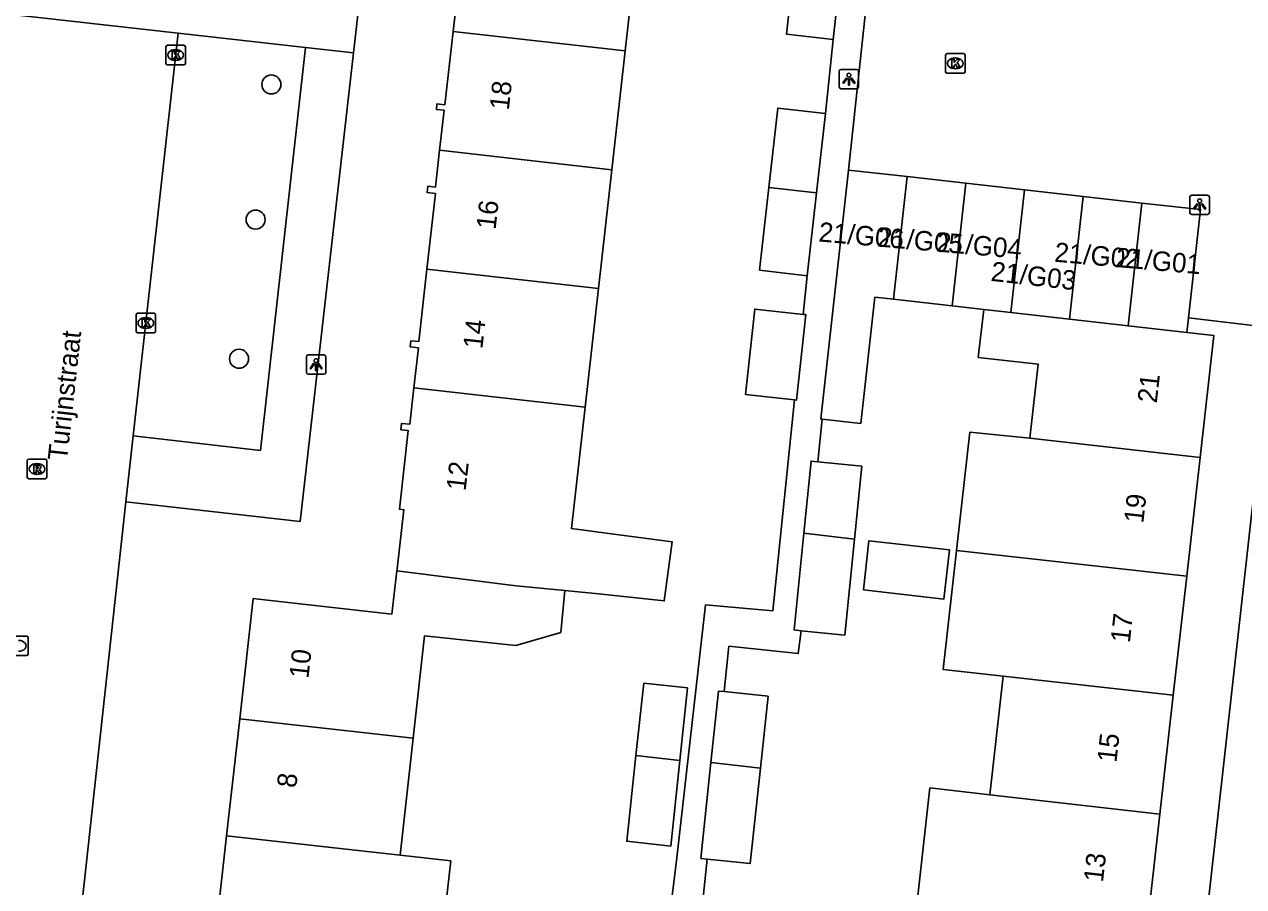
# Model space of a CAD drawing. Extents: x 162082 to 163393, y 388091 to 388632.
# Drawn here: x 162880.7 to 162943.3, y 388368.3 to 388412.6 of the extents above; entities that cross this region are included whole.
import ezdxf

# ---------------------------------------------------------------- set-up
doc = ezdxf.new("R2010")
doc.units = 0
for name, color, linetype in [('IMGEO_Boom', 7, 'Continuous'), ('IMGEO_Kolk', 7, 'Continuous'), ('IMGEO_Lichtpunt', 7, 'Continuous'), ('IMGEO_Openbare_ruimte_label', 7, 'Continuous'), ('IMGEO_Pand', 7, 'Continuous'), ('IMGEO_Pand_nummerreeks', 7, 'Continuous'), ('IMGEO_Rijbaan_lokaal_open', 7, 'Continuous'), ('IMGEO_Rioolput', 7, 'Continuous'), ('IMGEO_Voetpad_open', 7, 'Continuous')]:
    doc.layers.add(name, color=color, linetype=linetype)

msp = doc.modelspace()

# ---------------------------------------------------------------- linework, layer by layer
at = {"layer": 'IMGEO_Boom'}
for centre in [(162893.365, 388409.537), (162892.554, 388402.591), (162891.704, 388395.442)]:
    msp.add_circle(centre, 0.489, dxfattribs=at)
at = {"layer": 'IMGEO_Kolk'}
for p, q in [((162887.945, 388410.622), (162887.945, 388411.474)), ((162888.02, 388411.548), (162888.872, 388411.548)), ((162888.433, 388411.328), (162888.458, 388411.328)), ((162888.946, 388411.474), (162888.946, 388410.622)), ((162888.456, 388410.768), (162888.431, 388410.768)), ((162928.023, 388410.194), (162928.023, 388411.046)), ((162928.098, 388411.12), (162928.95, 388411.12)), ((162928.511, 388410.9), (162928.536, 388410.9)), ((162929.024, 388411.046), (162929.024, 388410.194)), ((162888.872, 388410.548), (162888.02, 388410.548)), ((162928.95, 388410.12), (162928.098, 388410.12)), ((162928.534, 388410.34), (162928.509, 388410.34)), ((162886.41, 388396.852), (162886.41, 388397.704)), ((162886.485, 388397.778), (162887.337, 388397.778)), ((162886.898, 388397.558), (162886.923, 388397.558)), ((162887.411, 388397.704), (162887.411, 388396.852)), ((162886.921, 388396.998), (162886.896, 388396.998)), ((162887.337, 388396.778), (162886.485, 388396.778)), ((162879.932, 388381.188), (162880.784, 388381.188)), ((162880.858, 388381.114), (162880.858, 388380.262)), ((162880.784, 388380.188), (162879.932, 388380.188))]:
    msp.add_line(p, q, dxfattribs=at)
for points in [[(162887.945, 388410.622), (162887.945, 388411.474)], [(162888.02, 388411.548), (162888.872, 388411.548)], [(162888.946, 388411.474), (162888.946, 388410.622)], [(162888.266, 388411.248), (162888.389, 388411.248), (162888.389, 388411.097), (162888.519, 388411.248), (162888.683, 388411.248), (162888.537, 388411.097), (162888.69, 388410.848), (162888.538, 388410.848), (162888.453, 388411.012), (162888.389, 388410.945), (162888.389, 388410.848), (162888.266, 388410.848), (162888.266, 388411.248)], [(162928.023, 388410.194), (162928.023, 388411.046)], [(162928.098, 388411.12), (162928.95, 388411.12)], [(162928.344, 388410.82), (162928.467, 388410.82), (162928.467, 388410.669), (162928.597, 388410.82), (162928.761, 388410.82), (162928.615, 388410.669), (162928.768, 388410.42), (162928.616, 388410.42), (162928.531, 388410.584), (162928.467, 388410.517), (162928.467, 388410.42), (162928.344, 388410.42), (162928.344, 388410.82)], [(162929.024, 388411.046), (162929.024, 388410.194)], [(162888.872, 388410.548), (162888.02, 388410.548)], [(162928.95, 388410.12), (162928.098, 388410.12)], [(162886.41, 388396.852), (162886.41, 388397.704)], [(162886.485, 388397.778), (162887.337, 388397.778)], [(162887.411, 388397.704), (162887.411, 388396.852)], [(162886.731, 388397.478), (162886.854, 388397.478), (162886.854, 388397.327), (162886.984, 388397.478), (162887.148, 388397.478), (162887.002, 388397.327), (162887.155, 388397.078), (162887.003, 388397.078), (162886.918, 388397.242), (162886.854, 388397.175), (162886.854, 388397.078), (162886.731, 388397.078), (162886.731, 388397.478)], [(162887.337, 388396.778), (162886.485, 388396.778)], [(162879.932, 388381.188), (162880.784, 388381.188)], [(162880.858, 388381.114), (162880.858, 388380.262)], [(162880.784, 388380.188), (162879.932, 388380.188)]]:
    msp.add_lwpolyline(points, dxfattribs=at)
for centre, start, end in [((162888.022, 388411.472), 91.55205, 178.44795), ((162888.022, 388411.472), 91.55205, 178.44795), ((162888.87, 388411.472), 1.55205, 88.44795), ((162888.87, 388411.472), 1.55205, 88.44795), ((162928.1, 388411.044), 91.55205, 178.44795), ((162928.1, 388411.044), 91.55205, 178.44795), ((162928.948, 388411.044), 1.55205, 88.44795), ((162928.948, 388411.044), 1.55205, 88.44795), ((162888.022, 388410.624), 181.55205, 268.44795), ((162888.022, 388410.624), 181.55205, 268.44795), ((162888.87, 388410.624), 271.55205, 358.44795), ((162888.87, 388410.624), 271.55205, 358.44795), ((162928.1, 388410.196), 181.55205, 268.44795), ((162928.1, 388410.196), 181.55205, 268.44795), ((162928.948, 388410.196), 271.55205, 358.44795), ((162928.948, 388410.196), 271.55205, 358.44795), ((162886.487, 388397.702), 91.55205, 178.44795), ((162886.487, 388397.702), 91.55205, 178.44795), ((162887.335, 388397.702), 1.55205, 88.44795), ((162887.335, 388397.702), 1.55205, 88.44795), ((162886.487, 388396.854), 181.55205, 268.44795), ((162886.487, 388396.854), 181.55205, 268.44795), ((162887.335, 388396.854), 271.55205, 358.44795), ((162887.335, 388396.854), 271.55205, 358.44795), ((162880.782, 388381.112), 1.55205, 88.44795), ((162880.782, 388381.112), 1.55205, 88.44795), ((162880.782, 388380.264), 271.55205, 358.44795), ((162880.782, 388380.264), 271.55205, 358.44795)]:
    msp.add_arc(centre, 0.0765, start, end, dxfattribs=at)
for centre, major_axis, ratio, start_param, end_param in [((162888.432, 388411.048), (-0.387, 0.002), 0.722429, 4.712389, 7.853982), ((162888.457, 388411.048), (-0.39, 0.002), 0.717154, 1.570796, 4.712389), ((162928.51, 388410.62), (-0.387, 0.002), 0.722429, 4.712389, 7.853982), ((162928.535, 388410.62), (-0.39, 0.002), 0.717154, 1.570796, 4.712389), ((162886.897, 388397.278), (-0.387, 0.002), 0.722429, 4.712389, 7.853982), ((162886.922, 388397.278), (-0.39, 0.002), 0.717154, 1.570796, 4.712389), ((162880.369, 388380.688), (-0.39, 0.002), 0.717154, 1.570796, 4.712389)]:
    msp.add_ellipse(centre, major_axis=major_axis, ratio=ratio, start_param=start_param, end_param=end_param, dxfattribs=at)
at = {"layer": 'IMGEO_Lichtpunt'}
for p, q in [((162922.555, 388410.214), (162922.555, 388409.407)), ((162922.555, 388410.214), (162922.555, 388409.407)), ((162923.457, 388410.309), (162922.649, 388410.309)), ((162923.457, 388410.309), (162922.649, 388410.309)), ((162923.551, 388409.407), (162923.551, 388410.214)), ((162923.551, 388409.407), (162923.551, 388410.214)), ((162922.649, 388409.313), (162923.457, 388409.313)), ((162922.649, 388409.313), (162923.457, 388409.313)), ((162941.486, 388403.849), (162940.678, 388403.849)), ((162941.486, 388403.849), (162940.678, 388403.849)), ((162940.584, 388403.754), (162940.584, 388402.947)), ((162940.584, 388403.754), (162940.584, 388402.947)), ((162941.58, 388402.947), (162941.58, 388403.754)), ((162941.58, 388402.947), (162941.58, 388403.754)), ((162940.678, 388402.853), (162941.486, 388402.853)), ((162940.678, 388402.853), (162941.486, 388402.853)), ((162895.164, 388395.543), (162895.164, 388394.736)), ((162895.164, 388395.543), (162895.164, 388394.736)), ((162896.066, 388395.638), (162895.258, 388395.638)), ((162896.066, 388395.638), (162895.258, 388395.638)), ((162896.16, 388394.736), (162896.16, 388395.543)), ((162896.16, 388394.736), (162896.16, 388395.543)), ((162895.258, 388394.642), (162896.066, 388394.642)), ((162895.258, 388394.642), (162896.066, 388394.642))]:
    msp.add_line(p, q, dxfattribs=at)
for points in [[(162922.929, 388409.878), (162922.968, 388409.85), (162922.78, 388409.588), (162922.742, 388409.615), (162922.929, 388409.878)], [(162923.031, 388409.83), (162923.078, 388409.83), (162923.078, 388409.508), (162923.031, 388409.508), (162923.031, 388409.83)], [(162923.141, 388409.85), (162923.179, 388409.877), (162923.366, 388409.615), (162923.327, 388409.587), (162923.141, 388409.85)], [(162940.958, 388403.418), (162940.997, 388403.39), (162940.809, 388403.128), (162940.771, 388403.155), (162940.958, 388403.418)], [(162941.06, 388403.37), (162941.107, 388403.37), (162941.107, 388403.048), (162941.06, 388403.048), (162941.06, 388403.37)], [(162941.17, 388403.39), (162941.208, 388403.417), (162941.395, 388403.155), (162941.356, 388403.127), (162941.17, 388403.39)], [(162895.538, 388395.207), (162895.577, 388395.179), (162895.389, 388394.917), (162895.351, 388394.944), (162895.538, 388395.207)], [(162895.64, 388395.159), (162895.687, 388395.159), (162895.687, 388394.837), (162895.64, 388394.837), (162895.64, 388395.159)], [(162895.75, 388395.179), (162895.788, 388395.206), (162895.975, 388394.944), (162895.936, 388394.916), (162895.75, 388395.179)]]:
    msp.add_lwpolyline(points, dxfattribs=at)
for centre in [(162923.054, 388410.012), (162941.083, 388403.552), (162895.663, 388395.341)]:
    msp.add_circle(centre, 0.0994, dxfattribs=at)
for centre, start, end in [((162922.649, 388410.214), 90, 180), ((162922.649, 388410.214), 90, 180), ((162923.457, 388410.214), 0, 90), ((162923.457, 388410.214), 0, 90), ((162922.649, 388409.407), 180, 270), ((162922.649, 388409.407), 180, 270), ((162923.457, 388409.407), 270, 0), ((162923.457, 388409.407), 270, 360), ((162940.678, 388403.754), 90, 180), ((162940.678, 388403.754), 90, 180), ((162941.486, 388403.754), 0, 90), ((162941.486, 388403.754), 0, 90), ((162940.678, 388402.947), 180, 270), ((162940.678, 388402.947), 180, 270), ((162941.486, 388402.947), 270, 0), ((162941.486, 388402.947), 270, 360), ((162895.258, 388395.543), 90, 180), ((162895.258, 388395.543), 90, 180), ((162896.066, 388395.543), 0, 90), ((162896.066, 388395.543), 0, 90), ((162895.258, 388394.736), 180, 270), ((162895.258, 388394.736), 180, 270), ((162896.066, 388394.736), 270, 0), ((162896.066, 388394.736), 270, 360)]:
    msp.add_arc(centre, 0.0946, start, end, dxfattribs=at)
at = {"layer": 'IMGEO_Pand'}
for points in [[(162902.702, 388412.256), (162903.148, 388416.214), (162902.781, 388416.255), (162902.811, 388416.521), (162903.195, 388416.477), (162903.406, 388418.355)], [(162912.234, 388417.362), (162911.547, 388411.261)], [(162920.323, 388416.452), (162919.845, 388412.119), (162922.249, 388411.854)], [(162922.726, 388416.182), (162922.249, 388411.854)], [(162902.011, 388406.155), (162902.242, 388408.213), (162901.847, 388408.257), (162901.879, 388408.54), (162902.279, 388408.495), (162902.702, 388412.256)], [(162902.702, 388412.256), (162911.547, 388411.261)], [(162911.547, 388411.261), (162910.861, 388405.158)], [(162918.94, 388404.248), (162919.397, 388408.322), (162921.845, 388408.047)], [(162921.845, 388408.047), (162921.388, 388403.972)], [(162901.361, 388400.05), (162901.798, 388403.932), (162901.367, 388403.98), (162901.404, 388404.306), (162901.798, 388404.262), (162902.011, 388406.155)], [(162910.861, 388405.158), (162902.011, 388406.155)], [(162910.861, 388405.158), (162910.175, 388399.057)], [(162921.673, 388392.337), (162921.601, 388392.345), (162922.33, 388398.836), (162923.038, 388405.139)], [(162923.038, 388405.139), (162926.054, 388404.8)], [(162926.054, 388404.8), (162925.345, 388398.497)], [(162929.069, 388404.461), (162926.054, 388404.8)], [(162929.069, 388404.461), (162928.361, 388398.158)], [(162932.084, 388404.122), (162929.069, 388404.461)], [(162918.94, 388404.248), (162918.461, 388399.985), (162920.909, 388399.71)], [(162921.388, 388403.972), (162918.94, 388404.248)], [(162921.388, 388403.972), (162920.909, 388399.71)], [(162932.084, 388404.122), (162931.376, 388397.819)], [(162935.1, 388403.784), (162932.084, 388404.122)], [(162934.392, 388397.479), (162935.1, 388403.784)], [(162938.116, 388403.445), (162935.1, 388403.784)], [(162937.407, 388397.136), (162938.116, 388403.445)], [(162940.506, 388397.545), (162941.131, 388403.106), (162938.116, 388403.445)], [(162900.69, 388393.946), (162900.921, 388395.998), (162900.502, 388396.045), (162900.538, 388396.369), (162900.942, 388396.323), (162901.361, 388400.05)], [(162901.361, 388400.05), (162910.175, 388399.057)], [(162910.175, 388399.057), (162909.488, 388392.955)], [(162925.345, 388398.497), (162924.387, 388398.605), (162923.658, 388392.114), (162921.673, 388392.337)], [(162928.361, 388398.158), (162925.345, 388398.497)], [(162928.361, 388398.158), (162929.983, 388397.976)], [(162920.255, 388393.333), (162917.737, 388393.606), (162918.213, 388397.992), (162920.705, 388397.722)], [(162920.705, 388397.722), (162920.84, 388397.707), (162920.365, 388393.321), (162920.255, 388393.333)], [(162929.983, 388397.976), (162929.705, 388395.506), (162932.788, 388395.16), (162932.36, 388391.355)], [(162931.376, 388397.819), (162929.983, 388397.976)], [(162931.376, 388397.819), (162934.392, 388397.479)], [(162940.422, 388396.793), (162940.506, 388397.545)], [(162937.407, 388397.136), (162934.392, 388397.479)], [(162940.422, 388396.793), (162937.407, 388397.136)], [(162941.102, 388390.373), (162941.806, 388396.638), (162940.422, 388396.793)], [(162899.813, 388384.536), (162899.826, 388384.65), (162900.177, 388387.679), (162899.946, 388387.705), (162900.401, 388391.746), (162900.022, 388391.789), (162900.059, 388392.122), (162900.479, 388392.074), (162900.69, 388393.946)], [(162909.488, 388392.955), (162900.69, 388393.946)], [(162908.448, 388383.527), (162910.351, 388383.344), (162913.563, 388382.992), (162913.961, 388386.033), (162910.712, 388386.458), (162908.786, 388386.71), (162909.488, 388392.955)], [(162932.36, 388391.355), (162929.274, 388391.674), (162928.59, 388385.584)], [(162932.36, 388391.355), (162941.102, 388390.373)], [(162920.735, 388386.471), (162921.11, 388390.186), (162921.452, 388390.152)], [(162923.337, 388386.178), (162923.714, 388389.924), (162921.452, 388390.152)], [(162940.415, 388384.26), (162941.102, 388390.373)], [(162920.59, 388381.467), (162920.235, 388381.503), (162920.735, 388386.471)], [(162920.735, 388386.471), (162923.337, 388386.178)], [(162920.59, 388381.467), (162922.839, 388381.241), (162923.337, 388386.178)], [(162923.796, 388383.56), (162924.08, 388386.084), (162928.223, 388385.625), (162927.939, 388383.094), (162923.796, 388383.56)], [(162928.59, 388385.584), (162927.904, 388379.474), (162930.986, 388379.128)], [(162940.415, 388384.26), (162931.673, 388385.242), (162928.59, 388385.584)], [(162891.739, 388376.944), (162892.43, 388383.113), (162893.007, 388383.048), (162899.555, 388382.315), (162899.813, 388384.536)], [(162908.448, 388383.527), (162905.942, 388383.767), (162899.813, 388384.536)], [(162939.729, 388378.146), (162940.415, 388384.26)], [(162900.655, 388375.945), (162901.243, 388381.196), (162905.937, 388380.699), (162908.242, 388381.377), (162908.448, 388383.527)], [(162912.105, 388375.059), (162912.503, 388378.769), (162914.762, 388378.527), (162914.362, 388374.794)], [(162930.302, 388373.037), (162930.986, 388379.128)], [(162930.986, 388379.128), (162939.729, 388378.146)], [(162915.963, 388374.684), (162916.354, 388378.366), (162916.638, 388378.336)], [(162918.502, 388374.393), (162918.894, 388378.097), (162916.638, 388378.336)], [(162939.729, 388378.146), (162939.042, 388372.033)], [(162891.065, 388370.923), (162891.739, 388376.944)], [(162891.739, 388376.944), (162900.655, 388375.945)], [(162900.655, 388375.945), (162899.981, 388369.924)], [(162914.362, 388374.794), (162913.892, 388370.4), (162911.632, 388370.642), (162912.105, 388375.059)], [(162912.105, 388375.059), (162914.362, 388374.794)], [(162915.764, 388369.733), (162915.442, 388369.767), (162915.963, 388374.684)], [(162915.764, 388369.733), (162917.982, 388369.497), (162918.502, 388374.393)], [(162915.963, 388374.684), (162918.502, 388374.393)], [(162930.302, 388373.037), (162927.218, 388373.384), (162926.526, 388367.229)], [(162939.042, 388372.033), (162930.302, 388373.037)], [(162938.355, 388365.919), (162939.042, 388372.033)], [(162890.391, 388364.901), (162891.065, 388370.923)], [(162891.065, 388370.923), (162899.981, 388369.924)], [(162899.981, 388369.924), (162902.587, 388369.632), (162901.913, 388363.61)]]:
    msp.add_lwpolyline(points, dxfattribs=at)
at = {"layer": 'IMGEO_Rijbaan_lokaal_open'}
for points in [[(162897.59, 388411.162), (162899.178, 388425.142)], [(162923.038, 388405.139), (162924.205, 388416)], [(162879.563, 388413.177), (162888.58, 388412.169)], [(162886.264, 388391.474), (162888.58, 388412.169)], [(162888.58, 388412.169), (162895.12, 388411.438)], [(162895.12, 388411.438), (162892.798, 388390.731), (162886.264, 388391.474)], [(162895.12, 388411.438), (162897.59, 388411.162)], [(162885.887, 388388.094), (162894.853, 388387.078), (162897.59, 388411.162)], [(162944.822, 388397.027), (162940.506, 388397.545)], [(162886.264, 388391.474), (162885.887, 388388.094)], [(162882.103, 388353.418), (162885.887, 388388.094)]]:
    msp.add_lwpolyline(points, dxfattribs=at)
at = {"layer": 'IMGEO_Rioolput'}
for p, q in [((162880.815, 388389.351), (162880.815, 388390.203)), ((162880.89, 388390.277), (162881.742, 388390.277)), ((162881.303, 388390.057), (162881.328, 388390.057)), ((162881.816, 388390.203), (162881.816, 388389.351)), ((162881.326, 388389.497), (162881.301, 388389.497)), ((162881.742, 388389.277), (162880.89, 388389.277))]:
    msp.add_line(p, q, dxfattribs=at)
for points in [[(162880.815, 388389.351), (162880.815, 388390.203)], [(162880.89, 388390.277), (162881.742, 388390.277)], [(162881.816, 388390.203), (162881.816, 388389.351)], [(162881.404, 388389.975), (162881.152, 388389.977), (162881.152, 388389.577)], [(162881.152, 388389.577), (162881.276, 388389.577), (162881.276, 388389.739), (162881.287, 388389.739)], [(162881.33, 388389.896), (162881.276, 388389.896), (162881.276, 388389.815)], [(162881.276, 388389.815), (162881.328, 388389.815)], [(162881.334, 388389.71), (162881.405, 388389.577), (162881.545, 388389.577), (162881.48, 388389.703)], [(162881.742, 388389.277), (162880.89, 388389.277)]]:
    msp.add_lwpolyline(points, dxfattribs=at)
for centre, radius, start, end in [((162880.892, 388390.201), 0.0765, 91.55205, 178.44795), ((162880.892, 388390.201), 0.0765, 91.55205, 178.44795), ((162881.74, 388390.201), 0.0765, 1.55205, 88.44795), ((162881.74, 388390.201), 0.0765, 1.55205, 88.44795), ((162881.286, 388389.686), 0.0533, 26.02933, 88.69889), ((162881.312, 388390.004), 0.19, 274.7715, 282.96867), ((162881.336, 388389.8), 0.0964, 77.00612, 93.18647), ((162881.35, 388389.857), 0.0378, 276.66336, 79.67722), ((162881.403, 388389.865), 0.109, 350.36119, 89.41601), ((162881.401, 388389.865), 0.112, 277.58423, 350.98172), ((162881.385, 388389.65), 0.108, 29.51342, 73.79051), ((162880.892, 388389.353), 0.0765, 181.55205, 268.44795), ((162880.892, 388389.353), 0.0765, 181.55205, 268.44795), ((162881.74, 388389.353), 0.0765, 271.55205, 358.44795), ((162881.74, 388389.353), 0.0765, 271.55205, 358.44795)]:
    msp.add_arc(centre, radius, start, end, dxfattribs=at)
for centre, major_axis, ratio, start_param, end_param in [((162881.302, 388389.777), (-0.387, 0.002), 0.722429, 4.712389, 7.853982), ((162881.327, 388389.777), (-0.39, 0.002), 0.717154, 1.570796, 4.712389)]:
    msp.add_ellipse(centre, major_axis=major_axis, ratio=ratio, start_param=start_param, end_param=end_param, dxfattribs=at)
at = {"layer": 'IMGEO_Voetpad_open'}
for points in [[(162922.249, 388411.854), (162921.845, 388408.047)], [(162920.909, 388399.71), (162920.705, 388397.722)], [(162944.822, 388397.027), (162944.742, 388396.308), (162939.248, 388347.057)], [(162920.255, 388393.333), (162919.141, 388382.481), (162915.683, 388382.791), (162914.215, 388369.801), (162912.564, 388356.407)], [(162921.452, 388390.152), (162921.673, 388392.337)], [(162916.638, 388378.336), (162916.886, 388380.668), (162920.45, 388380.287), (162920.59, 388381.467)], [(162915.395, 388366.129), (162915.764, 388369.733)]]:
    msp.add_lwpolyline(points, dxfattribs=at)

# ---------------------------------------------------------------- texts
at = {"layer": 'IMGEO_Openbare_ruimte_label'}
msp.add_text('Turijnstraat', height=1, rotation=83.68512, dxfattribs=at).set_placement((162882.858, 388390.17))
at = {"layer": 'IMGEO_Pand_nummerreeks'}
for s, rotation, p in [('18', 83.67268, (162905.569, 388408.189)), ('16', 83.67268, (162904.889, 388402.053)), ('21/G06', 355.08975, (162921.469, 388401.471)), ('21/G05', 355.08974, (162924.501, 388401.211)), ('21/G04', 355.08974, (162927.532, 388400.951)), ('21/G02', 355.08974, (162933.588, 388400.43)), ('21/G01', 355.08974, (162936.736, 388400.16)), ('21/G03', 353.56568, (162930.313, 388399.449)), ('14', 83.67268, (162904.209, 388395.92)), ('21', 83.59004, (162938.877, 388393.135)), ('12', 83.57735, (162903.35, 388388.625)), ('19', 83.59004, (162938.183, 388386.963)), ('17', 83.58881, (162937.492, 388380.812)), ('10', 83.61173, (162895.268, 388378.98)), ('15', 83.59004, (162936.801, 388374.661)), ('8', 83.61204, (162894.638, 388373.357)), ('13', 83.59004, (162936.11, 388368.51))]:
    msp.add_text(s, height=1, rotation=rotation, dxfattribs=at).set_placement(p)

doc.saveas('drawing.dxf')
